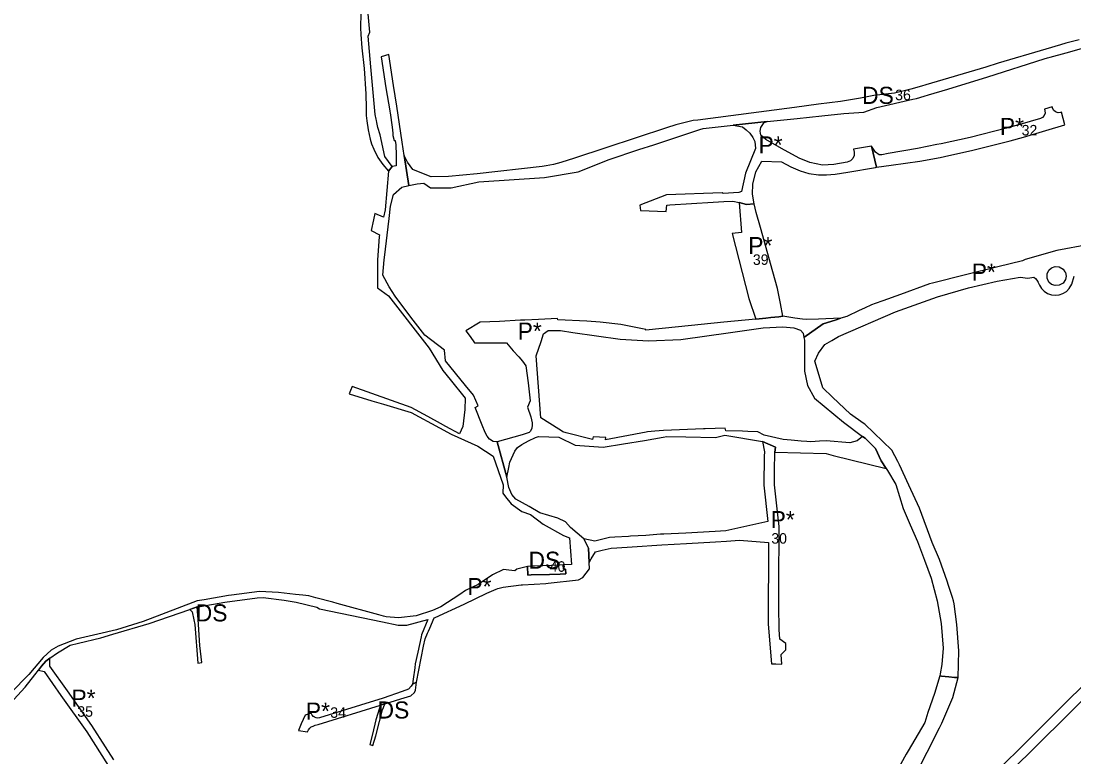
# Model space of a CAD drawing. Extents: x -535435 to -532834, y -1165802 to -1163866.
# Drawn here: x -534910 to -534109, y -1165258 to -1164698 of the extents above; entities that cross this region are included whole.
import ezdxf

# ---------------------------------------------------------------- set-up
doc = ezdxf.new("R2010")
doc.units = 0
for name, color, linetype in [('Level 23', 7, 'Continuous'), ('Level 4', 7, 'Continuous'), ('Level 43', 7, 'Continuous'), ('Level 44', 7, 'Continuous'), ('Level 5', 7, 'Continuous'), ('Level 61', 7, 'Continuous')]:
    doc.layers.add(name, color=color, linetype=linetype)

msp = doc.modelspace()

# ---------------------------------------------------------------- linework, layer by layer
at = {"layer": 'Level 23'}
msp.add_lwpolyline([(-534101.59, -1165203.84), (-534114.18, -1165216.32), (-534139.47, -1165241.41), (-534149.08, -1165250.94), (-534189.23, -1165290.59), (-534205.1, -1165305.99), (-534206.83, -1165307.61), (-534213.44, -1165313.82), (-534213.98, -1165314.34), (-534216.74, -1165316.93), (-534233.95, -1165326.61), (-534251.58, -1165333.78), (-534251.69, -1165338.72), (-534251.77, -1165341.96), (-534230.69, -1165333.38), (-534212.27, -1165323.02), (-534205.31, -1165316.61), (-534200.89, -1165312.54), (-534194.29, -1165306.12), (-534136.8, -1165249.37), (-534066.72, -1165179.82)], dxfattribs=at)
at = {"layer": 'Level 4'}
for points in [[(-534779.24, -1165147.77), (-534778.07, -1165153.71), (-534777.36, -1165157.3), (-534774.98, -1165186.88), (-534772.09, -1165186.32), (-534773.45, -1165173.38), (-534774.56, -1165157.32), (-534774.83, -1165153.47), (-534775.05, -1165150.33), (-534775.25, -1165147.5), (-534775.49, -1165144.03), (-534781.08, -1165145.96), (-534779.24, -1165147.77)], [(-534225.18, -1165263.79), (-534220.39, -1165254.46), (-534210.89, -1165236.07), (-534209.06, -1165232.51), (-534200.78, -1165212.83), (-534196.74, -1165197.75), (-534199.6, -1165197.58), (-534203.7, -1165197.09), (-534209.35, -1165196.56), (-534210.61, -1165196.44), (-534214.76, -1165209.81), (-534219.65, -1165224.42), (-534222.12, -1165231.81), (-534234.65, -1165253.49), (-534236.16, -1165256.09), (-534249.84, -1165280.89)], [(-534636.15, -1165218.67), (-534636.93, -1165221.04), (-534639.56, -1165229.81), (-534642.21, -1165240.82), (-534644.29, -1165248.75), (-534641.82, -1165249.4), (-534639.72, -1165242.1), (-534636.98, -1165231.14), (-534634.63, -1165222.23), (-534633.92, -1165220.53), (-534632.69, -1165217.6), (-534636.15, -1165218.67)]]:
    msp.add_lwpolyline(points, dxfattribs=at)
at = {"layer": 'Level 43'}
for points in [[(-534915.11, -1165214.3), (-534906.33, -1165204.96), (-534899, -1165195.56), (-534896.25, -1165192.04), (-534893.87, -1165188.98), (-534890.71, -1165185.18), (-534887.58, -1165182.94), (-534881.84, -1165178.84), (-534872.13, -1165173.18), (-534865.77, -1165171.59), (-534848.93, -1165167.39), (-534839.59, -1165164.67), (-534812.16, -1165156.7), (-534781.08, -1165145.96), (-534775.49, -1165144.03), (-534773.4, -1165143.64), (-534754.46, -1165140.25), (-534729.95, -1165137.1), (-534725.42, -1165136.87), (-534709.27, -1165138.78), (-534700.3, -1165140.27), (-534684.51, -1165144.15), (-534682.61, -1165145.33), (-534634.67, -1165155.34), (-534622.58, -1165157.86), (-534616.15, -1165157.87), (-534600.19, -1165153.5), (-534604.96, -1165165.29), (-534605.25, -1165166.64), (-534607.79, -1165178.29), (-534609.72, -1165187.18), (-534610.1, -1165190.23), (-534611.2, -1165198.9), (-534611.73, -1165202.83), (-534608.72, -1165201.29), (-534603.51, -1165173.76), (-534602.14, -1165168.33), (-534600.32, -1165164.01), (-534599.6, -1165162.33), (-534598.66, -1165160.11), (-534595.36, -1165152.25), (-534594.43, -1165152.01), (-534572.34, -1165142), (-534555.22, -1165133.48), (-534548.1, -1165130.49), (-534546.81, -1165129.93), (-534542.89, -1165128.92), (-534529.03, -1165127.13), (-534527.96, -1165127.06), (-534510.46, -1165126.27), (-534508.47, -1165126.04), (-534485.47, -1165123.31), (-534482.11, -1165121.5), (-534477.12, -1165115.1), (-534477.36, -1165110.2), (-534477.91, -1165099.28), (-534481.55, -1165092.07), (-534491.48, -1165083.48), (-534495.29, -1165079.16), (-534501.27, -1165076.38), (-534514.83, -1165072.36), (-534523.11, -1165067.68), (-534533.08, -1165062.06), (-534536.12, -1165058.39), (-534538.55, -1165053.24), (-534540.03, -1165045.35), (-534547.38, -1165018.35), (-534550.49, -1165018.12), (-534553.07, -1165016.4), (-534554.89, -1165013.98), (-534556.42, -1165011.31), (-534558.89, -1165005.68), (-534564.1, -1164992.18), (-534561.82, -1164991.02), (-534565.31, -1164982.96), (-534571.32, -1164975.54), (-534586.6, -1164956.69), (-534587.3, -1164948.74), (-534602.43, -1164937.26), (-534612.91, -1164923.42), (-534624.92, -1164907.57), (-534629.53, -1164900.39), (-534634.21, -1164891.59), (-534633.32, -1164879.93), (-534633.15, -1164878.09), (-534629.49, -1164848.51), (-534628.39, -1164839.07), (-534626.3, -1164830.31), (-534619.84, -1164824.52), (-534614.56, -1164823.48), (-534618.03, -1164800.56), (-534619.57, -1164790.4), (-534623.71, -1164763.1), (-534626.11, -1164747.28), (-534629.67, -1164723.78), (-534635.7, -1164725.53), (-534631.92, -1164749.04), (-534629.1, -1164766.51), (-534628.99, -1164767.2), (-534628.86, -1164767.99), (-534627.14, -1164778.96), (-534626.84, -1164783.65), (-534626.73, -1164785.43), (-534625.82, -1164789.15), (-534624.82, -1164789.03), (-534624.44, -1164792.41), (-534624.07, -1164800.22), (-534624.26, -1164808.39), (-534627.21, -1164808.9), (-534629.93, -1164812.5), (-534632.65, -1164841.86), (-534633.89, -1164847.54), (-534640.46, -1164844.56), (-534641.49, -1164849.43), (-534643.23, -1164857.71), (-534636.79, -1164860.82), (-534637.16, -1164862.5), (-534638.46, -1164879.94), (-534638.46, -1164886.69), (-534638.31, -1164895.93), (-534638.33, -1164901.25), (-534630.14, -1164907.3), (-534599.05, -1164947.01), (-534588.73, -1164964), (-534583.16, -1164970.86), (-534571.66, -1164985.07), (-534571.86, -1164993.7), (-534573.45, -1165006.71), (-534576.08, -1165012.33), (-534586.35, -1165006.69), (-534590.54, -1165004.41), (-534600.2, -1164999.12), (-534612.8, -1164992.22), (-534657.76, -1164976.32), (-534659.02, -1164979.39), (-534659.81, -1164981.95), (-534642.59, -1164987.17), (-534633.77, -1164989.84), (-534612.88, -1164996.18), (-534591.32, -1165007.75), (-534582.3, -1165012.59), (-534577.2, -1165014.85), (-534562.04, -1165021.58), (-534550.39, -1165029.21), (-534542.87, -1165051.15), (-534543.04, -1165057.57), (-534540.96, -1165060.2), (-534536.79, -1165065.58), (-534528.58, -1165071.39), (-534522.06, -1165073.71), (-534512.37, -1165081.09), (-534496.83, -1165089.67), (-534492.42, -1165091.46), (-534490.8, -1165111.76), (-534497.04, -1165112.02), (-534496.95, -1165115.27), (-534495.36, -1165115.23), (-534495.25, -1165118.92), (-534499.45, -1165119.04), (-534507.64, -1165119.26), (-534521.53, -1165119.64), (-534523.98, -1165119.71), (-534524.4, -1165113.2), (-534532.37, -1165115.29), (-534533.82, -1165116.64), (-534538.48, -1165116.07), (-534542.44, -1165115.58), (-534551, -1165119.46), (-534561.87, -1165126.95), (-534571.4, -1165131.42), (-534575.87, -1165134.42), (-534590.09, -1165143.97), (-534596.6, -1165146.72), (-534608.98, -1165150.83), (-534622.29, -1165152.23), (-534631.91, -1165151.48), (-534633.91, -1165151.11), (-534637.49, -1165150.02), (-534669, -1165141.45), (-534672.46, -1165140.44), (-534685.34, -1165137.05), (-534690.72, -1165135.63), (-534695.14, -1165134.96), (-534700.81, -1165134.43), (-534713.68, -1165132.97), (-534728.23, -1165132.15), (-534749.51, -1165134.97), (-534751.63, -1165135.33), (-534770.12, -1165138.51), (-534775.57, -1165139.44), (-534802.57, -1165149.67), (-534816.66, -1165154.98), (-534836.95, -1165161.52), (-534851.12, -1165164.76), (-534867.51, -1165168.45), (-534881.29, -1165173.85), (-534886.69, -1165177.01), (-534892.73, -1165182.38), (-534903.6, -1165195.4), (-534917.33, -1165209.45)], [(-534342.09, -1164774.76), (-534367.86, -1164777.52), (-534360.7, -1164778.68), (-534357.92, -1164781.04), (-534355.09, -1164783.45), (-534352.77, -1164786.79), (-534351.44, -1164789.84), (-534350.81, -1164795.27), (-534358.41, -1164814.11), (-534361.56, -1164828.03), (-534363.61, -1164828.81), (-534375.55, -1164829.48), (-534376.12, -1164829.05), (-534418.52, -1164830.41), (-534438.72, -1164838.43), (-534438.32, -1164842.42), (-534418.77, -1164843.03), (-534418.37, -1164838.3), (-534415.92, -1164838.06), (-534383.14, -1164836.16), (-534375.03, -1164835.57), (-534368.16, -1164835.29), (-534363.3, -1164836.43), (-534357.64, -1164837.76), (-534351.84, -1164837.24), (-534353.07, -1164830.03), (-534352.88, -1164822.3), (-534350.53, -1164813.01), (-534346.02, -1164804.74), (-534331.17, -1164805.49), (-534324, -1164809.24), (-534316.94, -1164812.28), (-534310.16, -1164814.2), (-534303.02, -1164815.23), (-534296.93, -1164815.35), (-534290.15, -1164814.7), (-534280.7, -1164813.17), (-534259.51, -1164809.65), (-534258.75, -1164809.52), (-534262.71, -1164793.42), (-534276.18, -1164795.73), (-534275.8, -1164798.11), (-534275.85, -1164800.57), (-534276.78, -1164802.81), (-534278.66, -1164804.69), (-534281.07, -1164805.63), (-534291.34, -1164807.29), (-534299.79, -1164807.88), (-534309.48, -1164805.76), (-534317.68, -1164802.59), (-534331.09, -1164795.19), (-534342.89, -1164788.41), (-534346.92, -1164785.05), (-534347.25, -1164782.06), (-534346.92, -1164779.3), (-534344.16, -1164775.52), (-534342.09, -1164774.76)], [(-534096.94, -1164868.25), (-534121.57, -1164872.72), (-534145.84, -1164879.67), (-534147.77, -1164880.61), (-534166.53, -1164885.27), (-534191.06, -1164891.36), (-534216.19, -1164897.61), (-534218.39, -1164898.16), (-534240.59, -1164906.25), (-534253.91, -1164911.1), (-534259.85, -1164913.26), (-534262.64, -1164914.28), (-534268, -1164916.74), (-534271.94, -1164918.56), (-534281.43, -1164922.93), (-534285.82, -1164924.34), (-534290.19, -1164925.73), (-534299.38, -1164928.68), (-534313.98, -1164938.94), (-534313.54, -1164941.08), (-534313.54, -1164953.57), (-534313.47, -1164964.73), (-534311.34, -1164975.55), (-534305.86, -1164985.22), (-534283.92, -1165003.31), (-534269.44, -1165014.34), (-534267.31, -1165015.58), (-534259.6, -1165023.45), (-534255.38, -1165032.78), (-534251.41, -1165038.78), (-534250.52, -1165040.21), (-534244.03, -1165050.78), (-534238.41, -1165069.05), (-534233.08, -1165081.58), (-534227.74, -1165094.09), (-534222.38, -1165108.41), (-534217.22, -1165122.23), (-534212.54, -1165139.35), (-534209.51, -1165156.58)], [(-534125.62, -1164898.63), (-534127.71, -1164896.82), (-534129.09, -1164893.96), (-534129.09, -1164891.38), (-534129.09, -1164890.62), (-534127.71, -1164887.75), (-534125.62, -1164885.94), (-534123, -1164885.03), (-534119.83, -1164885.27), (-534116.94, -1164886.94), (-534115.56, -1164888.96), (-534115.15, -1164889.57), (-534114.63, -1164892.29), (-534115.15, -1164895.01), (-534116.94, -1164897.63), (-534119.83, -1164899.3), (-534123, -1164899.54), (-534125.62, -1164898.63)], [(-534209.51, -1165156.58), (-534208.19, -1165175.29), (-534209.14, -1165187.8), (-534210.33, -1165194.82), (-534210.61, -1165196.44), (-534209.35, -1165196.56), (-534203.7, -1165197.09), (-534199.6, -1165197.58), (-534196.74, -1165197.75), (-534196.09, -1165177.34), (-534197.6, -1165157.43), (-534199.83, -1165141.58), (-534200.14, -1165139.35), (-534201, -1165136.72), (-534203.92, -1165127.62), (-534204.94, -1165124.43), (-534211.01, -1165107.94), (-534216.42, -1165094.93), (-534226.11, -1165068.82), (-534234.19, -1165051.24), (-534241.2, -1165036.01), (-534242.54, -1165033.34), (-534247.06, -1165024.76), (-534267.81, -1165004.92), (-534268.88, -1165004.18), (-534278.67, -1164997.45), (-534292.25, -1164984.51), (-534299.71, -1164977.41), (-534302.49, -1164968.05), (-534305.74, -1164957.13), (-534302.89, -1164950.93), (-534298.12, -1164944.44), (-534292.74, -1164941.26), (-534287.71, -1164938.27), (-534244.36, -1164919.45), (-534212.46, -1164908.12), (-534188.71, -1164901.35), (-534166.92, -1164896.21), (-534149.48, -1164893.03), (-534143.59, -1164893.98), (-534139.15, -1164893.18), (-534137.85, -1164894.21), (-534136.17, -1164896.41), (-534136.05, -1164896.57), (-534134.79, -1164899.23), (-534133.26, -1164901.76), (-534131.19, -1164903.88), (-534128.69, -1164905.48), (-534125.82, -1164906.5), (-534122.74, -1164906.88), (-534119.83, -1164906.52), (-534117.01, -1164905.53), (-534114.35, -1164903.98), (-534112.2, -1164901.85), (-534110.31, -1164898.33), (-534108.42, -1164892.42)], [(-534345.52, -1165018.15), (-534335.68, -1165022.47), (-534336.09, -1165026.21), (-534297.22, -1165027.38), (-534291.71, -1165028.75), (-534251.41, -1165038.78), (-534255.38, -1165032.78), (-534259.6, -1165023.45), (-534267.31, -1165015.58), (-534269.44, -1165014.34), (-534273.42, -1165017.68), (-534279.05, -1165019.05), (-534296.99, -1165017.68), (-534302.11, -1165018.01), (-534308.77, -1165018.44), (-534311.71, -1165018.18), (-534316.13, -1165017.8), (-534323.68, -1165017.15), (-534329.82, -1165016.63), (-534344.37, -1165013.33), (-534348.99, -1165010.79), (-534356.63, -1165010.51), (-534360.64, -1165010.37), (-534373.42, -1165009.91), (-534374.04, -1165007.87), (-534389.11, -1165008.45), (-534390.4, -1165008.5), (-534420.92, -1165009.8), (-534427.49, -1165010.4), (-534433.05, -1165010.9), (-534434.11, -1165010.99), (-534464.85, -1165016.92), (-534464.79, -1165015.17), (-534474.29, -1165014.68), (-534474.77, -1165016.57), (-534494.86, -1165011.42), (-534497.44, -1165010.75), (-534499.22, -1165009.6), (-534500.57, -1165008.73), (-534514.1, -1165000.01), (-534517.7, -1164953.01), (-534513.99, -1164941.98), (-534512.2, -1164936.18), (-534508.63, -1164933.76), (-534499.19, -1164933.76), (-534489.85, -1164935.13), (-534453.8, -1164940.4), (-534432.19, -1164941.66), (-534407.72, -1164940.46), (-534369.99, -1164935.23), (-534344.91, -1164931.76), (-534330.15, -1164930.91), (-534321.61, -1164931.63), (-534316.65, -1164933.55), (-534314.65, -1164935.66), (-534313.98, -1164938.94), (-534299.38, -1164928.68), (-534290.19, -1164925.73), (-534285.82, -1164924.34), (-534302.96, -1164925.05), (-534312.36, -1164925.44), (-534315.05, -1164925.05), (-534320.81, -1164924.23), (-534329.95, -1164922.91), (-534333.22, -1164923.24), (-534339.28, -1164923.85), (-534342.99, -1164924.23), (-534350.56, -1164925), (-534375.06, -1164927.47), (-534409.31, -1164930.93), (-534434.37, -1164933.46), (-534434.25, -1164932.97), (-534453.19, -1164929.01), (-534469.12, -1164927.47), (-534479.05, -1164926.51), (-534501.29, -1164925.46), (-534501.38, -1164924.52), (-534515.85, -1164925.23), (-534526.26, -1164925.74), (-534529.29, -1164925.89), (-534529.67, -1164925.9), (-534545.54, -1164926.82), (-534560.34, -1164927.43), (-534571.09, -1164933.92), (-534567.81, -1164938.28), (-534564.69, -1164943.03), (-534540.3, -1164943.15), (-534535.29, -1164949.09), (-534530.94, -1164953.79), (-534528.03, -1164956.95), (-534525.63, -1164960.55), (-534523.76, -1164973.56), (-534522.25, -1164987.18), (-534524.23, -1164991.91), (-534521.78, -1164999.46), (-534520.8, -1165003.96), (-534520.65, -1165005.82), (-534520.93, -1165008.08), (-534521.91, -1165010.32), (-534522.94, -1165011.32), (-534528.3, -1165013.15), (-534547.38, -1165018.35), (-534540.03, -1165045.35), (-534538.58, -1165038), (-534537.78, -1165033.97), (-534534.04, -1165025.41), (-534531.91, -1165022.8), (-534528.72, -1165020.51), (-534523.64, -1165017.68), (-534518.13, -1165015.17), (-534515.85, -1165014.39), (-534508.03, -1165014.6), (-534500.56, -1165014.81), (-534488.01, -1165020.91), (-534466.76, -1165022.45), (-534451.2, -1165019.87), (-534435.41, -1165017.27), (-534420.99, -1165014.89), (-534418.3, -1165014.45), (-534403.97, -1165014.71), (-534381.21, -1165015.12), (-534374.22, -1165013.39), (-534345.52, -1165018.15)]]:
    msp.add_lwpolyline(points, dxfattribs=at)
at = {"layer": 'Level 44'}
for points in [[(-534115.53, -1164777.34), (-534117.99, -1164767.64), (-534118.86, -1164767.9), (-534120.73, -1164768.07), (-534122.67, -1164767.45), (-534124.2, -1164766.1), (-534125, -1164764.4), (-534125.22, -1164763.52), (-534130.98, -1164765.22), (-534130.66, -1164766.48), (-534130.54, -1164768.27), (-534131.15, -1164770.1), (-534132.42, -1164771.56), (-534134.02, -1164772.38), (-534149.67, -1164777), (-534159.87, -1164779.82), (-534187.68, -1164786.81), (-534209.64, -1164791.61), (-534212.93, -1164792.28), (-534227.74, -1164795.15), (-534249.82, -1164799.1), (-534254.78, -1164799.96), (-534256.66, -1164800.01), (-534259.63, -1164798), (-534262.71, -1164793.42), (-534258.75, -1164809.52), (-534247.6, -1164807.98), (-534225.91, -1164804.98), (-534210.38, -1164801.97), (-534207.12, -1164801.3), (-534185.41, -1164796.55), (-534157.26, -1164789.48), (-534146.94, -1164786.62), (-534115.53, -1164777.34)], [(-534839.01, -1165260.41), (-534845.4, -1165250.42), (-534855.59, -1165234.29), (-534874.3, -1165207.84), (-534887.6, -1165189.06), (-534887.58, -1165182.94), (-534890.71, -1165185.18), (-534893.87, -1165188.98), (-534896.25, -1165192.04), (-534891.91, -1165193.17), (-534879.2, -1165211.3), (-534859.49, -1165238.97), (-534843.37, -1165264.7)]]:
    msp.add_lwpolyline(points, dxfattribs=at)
for points in [[(-534351.84, -1164837.24), (-534357.64, -1164837.76), (-534363.3, -1164836.43), (-534361.45, -1164859.01), (-534368.71, -1164859.96), (-534355.92, -1164909.3), (-534350.56, -1164925), (-534342.99, -1164924.23), (-534339.28, -1164923.85), (-534333.22, -1164923.24), (-534329.95, -1164922.91), (-534331.9, -1164913.07), (-534334.14, -1164901.79), (-534337.71, -1164889.02), (-534347.13, -1164855.26), (-534350.27, -1164844.02)], [(-534362.94, -1165093.25), (-534340.94, -1165094.96), (-534341.17, -1165157.05), (-534338.8, -1165187.24), (-534335.39, -1165187.36), (-534330.75, -1165187.54), (-534331.33, -1165180.12), (-534327.9, -1165176.67), (-534327.9, -1165174.27), (-534327.9, -1165171.87), (-534332.24, -1165168.56), (-534332.82, -1165161.24), (-534333.12, -1165143.49), (-534333.05, -1165125.22), (-534333.01, -1165112.19), (-534332.96, -1165098.52), (-534332.92, -1165086.14), (-534332.91, -1165082.8), (-534333.89, -1165074.02), (-534336.45, -1165051.12), (-534336.35, -1165040.51), (-534336.09, -1165026.21), (-534335.68, -1165022.47), (-534345.52, -1165018.15), (-534344.09, -1165026.06), (-534344.15, -1165029.23), (-534344.45, -1165051.28), (-534341.36, -1165078.89), (-534373.53, -1165086), (-534381.51, -1165086.49), (-534403.97, -1165087.87), (-534420.53, -1165088.55), (-534420.94, -1165088.56), (-534423.1, -1165088.71), (-534434.26, -1165089.65), (-534445.83, -1165090.22), (-534447.57, -1165090.34), (-534457.81, -1165091.02), (-534461.79, -1165091.28), (-534468.89, -1165092.92), (-534473.09, -1165093.89), (-534481.55, -1165092.07), (-534477.91, -1165099.28), (-534477.36, -1165110.2), (-534475.74, -1165107.41), (-534472.58, -1165101.98), (-534467.43, -1165100.79), (-534460.62, -1165099.22), (-534456.21, -1165098.93), (-534444.71, -1165098.16), (-534422.06, -1165096.67), (-534403.26, -1165095.84), (-534381.17, -1165094.48), (-534372.9, -1165093.98)], [(-534619.67, -1165208.32), (-534634.06, -1165213.3), (-534682.53, -1165228.33), (-534683.94, -1165228.55), (-534684.96, -1165228.47), (-534686.33, -1165227.95), (-534687.13, -1165227.39), (-534687.28, -1165227.29), (-534688.1, -1165226.32), (-534688.82, -1165224.82), (-534689.62, -1165225.09), (-534693.46, -1165226.39), (-534696.45, -1165232.95), (-534698.45, -1165238.1), (-534691.61, -1165239), (-534690.96, -1165237.55), (-534689.97, -1165236.28), (-534688.72, -1165235.28), (-534687.31, -1165234.61), (-534685.72, -1165234.06), (-534683.4, -1165233.35), (-534636.15, -1165218.67), (-534632.69, -1165217.6), (-534620.57, -1165213.91), (-534613.07, -1165211.63), (-534610.14, -1165208.97), (-534609.41, -1165207.24), (-534608.72, -1165201.29), (-534611.73, -1165202.83), (-534612.86, -1165204.39), (-534614.69, -1165206.46)]]:
    msp.add_lwpolyline(points, close=True, dxfattribs=at)
at = {"layer": 'Level 5'}
for points in [[(-534650.97, -1164692.25), (-534651.25, -1164703.41), (-534651.06, -1164708.53), (-534650.18, -1164718.67), (-534648.65, -1164734.35), (-534647.32, -1164753.72), (-534647, -1164764.5), (-534646.88, -1164770.14), (-534646.54, -1164774.16), (-534645.4, -1164780.98), (-534643.96, -1164788.25), (-534642.85, -1164791.65), (-534641.2, -1164795.66), (-534638.14, -1164801.98), (-534634.38, -1164807.47), (-534629.93, -1164812.5), (-534627.21, -1164808.9), (-534632.72, -1164801.19), (-534636.46, -1164784.72), (-534638.06, -1164779.14), (-534638.85, -1164775.39), (-534639.18, -1164773.81), (-534639.37, -1164772.85), (-534640.1, -1164769.32), (-534643.47, -1164733.09), (-534645.6, -1164709.73), (-534644.26, -1164706.72), (-534645.38, -1164692.75)], [(-534104.66, -1164712.55), (-534114.9, -1164715.1), (-534118.87, -1164716.27), (-534130.02, -1164719.57), (-534166.14, -1164730.4), (-534175.74, -1164733.28), (-534221.26, -1164746.89), (-534224.58, -1164747.89), (-534232.71, -1164750.03), (-534245.02, -1164753.04), (-534260.89, -1164754.97), (-534270.96, -1164756.82), (-534286.07, -1164759.45), (-534302.83, -1164761.62), (-534321.12, -1164764), (-534369.62, -1164770.28), (-534394.78, -1164773.55), (-534398.19, -1164773.99), (-534411.44, -1164777.13), (-534418.65, -1164779.51), (-534464.63, -1164794.65), (-534488.48, -1164802.49), (-534498.81, -1164805.87), (-534504.58, -1164807.36), (-534510.13, -1164808.51), (-534513.08, -1164808.97), (-534562.68, -1164814.45), (-534584.38, -1164816.45), (-534597.57, -1164816.73), (-534607.18, -1164812.97), (-534611.45, -1164811.19), (-534615.55, -1164805.6), (-534618.03, -1164800.56), (-534614.56, -1164823.48), (-534608.11, -1164822.09), (-534603.04, -1164821.68), (-534598.14, -1164825.08), (-534582.32, -1164825.13), (-534561.27, -1164820.66), (-534511.37, -1164817.22), (-534485.79, -1164812.88), (-534462.18, -1164803.59), (-534439.58, -1164796.11), (-534428.15, -1164792.33), (-534416.78, -1164788.57), (-534393.08, -1164780.73), (-534390.78, -1164779.97), (-534367.86, -1164777.52), (-534342.09, -1164774.76), (-534319.12, -1164772.3), (-534300.47, -1164770.31), (-534283.7, -1164768.52), (-534268.47, -1164767.68), (-534258.61, -1164764.08), (-534231.06, -1164757.76), (-534228.45, -1164757.2), (-534222.59, -1164755.48), (-534219.28, -1164754.49), (-534204.47, -1164750.16), (-534174.08, -1164740.65), (-534131.26, -1164726.94), (-534128.72, -1164726.22), (-534126.83, -1164725.69), (-534114.47, -1164722.35), (-534102.86, -1164719.22)], [(-534523.98, -1165119.71), (-534521.53, -1165119.64), (-534507.64, -1165119.26), (-534499.45, -1165119.04), (-534495.25, -1165118.92), (-534495.36, -1165115.23), (-534496.95, -1165115.27), (-534497.04, -1165112.02), (-534499.64, -1165112.1), (-534519.03, -1165112.95), (-534521.96, -1165113.08), (-534524.4, -1165113.2), (-534523.98, -1165119.71)]]:
    msp.add_lwpolyline(points, dxfattribs=at)

# ---------------------------------------------------------------- texts
at = {"layer": 'Level 4'}
for p in [(-534776.64, -1165155.02), (-534638.34, -1165228.89)]:
    msp.add_text('DS', height=13, dxfattribs=at).set_placement(p)
at = {"layer": 'Level 43'}
for p in [(-534348.57, -1164799), (-534186.33, -1164895.75), (-534531.78, -1164940.62), (-534570, -1165135)]:
    msp.add_text('P*', height=13, dxfattribs=at).set_placement(p)
at = {"layer": 'Level 44'}
for p in [(-534165, -1164785), (-534356.38, -1164875.54), (-534339.34, -1165084.06), (-534871.18, -1165219.9), (-534692.91, -1165229.74)]:
    msp.add_text('P*', height=13, dxfattribs=at).set_placement(p)
at = {"layer": 'Level 5'}
for p in [(-534269.79, -1164761.28), (-534523.52, -1165114.96)]:
    msp.add_text('DS', height=13, dxfattribs=at).set_placement(p)
at = {"layer": 'Level 61'}
for s, p in [('36', (-534244.59, -1164758.48)), ('32', (-534148.39, -1164785.3)), ('39', (-534352.83, -1164883.77)), ('30', (-534338.82, -1165095.86)), ('40', (-534507.35, -1165117.25)), ('35', (-534866.72, -1165227.57)), ('34', (-534674.29, -1165228.36))]:
    msp.add_text(s, height=8, dxfattribs=at).set_placement(p)

doc.saveas('drawing.dxf')
